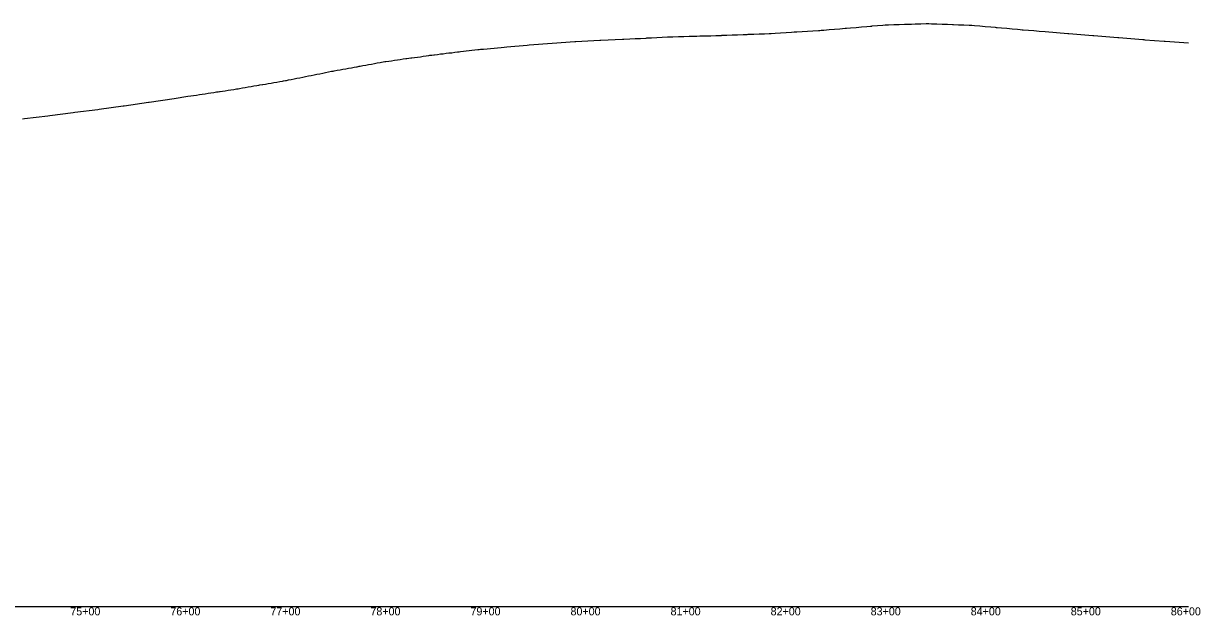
# Model space of a CAD drawing. Extents: x 49922 to 54713, y 49991 to 62800.
# Drawn here: x 53436 to 54612, y 49991 to 50583 of the extents above; entities that cross this region are included whole.
import ezdxf

# ---------------------------------------------------------------- set-up
doc = ezdxf.new("R2010")
doc.units = 0
for name, color, linetype in [('RD_DDB_Profile_EX', 7, 'Continuous'), ('RD_DDB_StaTX', 7, 'Continuous'), ('RD_GPK_Profile_Cell', 7, 'Continuous')]:
    doc.layers.add(name, color=color, linetype=linetype)

msp = doc.modelspace()

# ---------------------------------------------------------------- linework, layer by layer
at = {"layer": 'RD_DDB_Profile_EX'}
for points in [[(54052.5, 50567.8), (54057.9, 50568.1), (54058.6, 50568.2), (54060.7, 50568.2), (54063.3, 50568.4), (54068.6, 50568.6), (54074, 50568.9), (54079.4, 50569.2), (54081.6, 50569.3), (54083.8, 50569.4), (54084.8, 50569.4), (54090.2, 50569.6), (54095.6, 50569.7), (54100.9, 50569.9), (54106, 50570), (54106.3, 50570), (54108.8, 50570.1), (54111.7, 50570.2), (54117.1, 50570.3), (54122.5, 50570.5), (54127.8, 50570.7), (54130.7, 50570.7), (54133.2, 50570.8), (54133.6, 50570.9), (54138.6, 50571), (54144, 50571.2), (54149.4, 50571.5), (54154.8, 50571.7), (54155.7, 50571.7), (54158.6, 50571.8), (54159.1, 50571.8), (54160.1, 50571.9), (54165.5, 50572.1), (54170.9, 50572.3), (54176.3, 50572.5), (54181, 50572.7), (54181.7, 50572.7), (54183, 50572.8), (54187.1, 50573.1), (54192.4, 50573.4), (54197.8, 50573.7), (54203.2, 50574.1), (54205.8, 50574.2), (54208, 50574.4), (54208.6, 50574.4), (54214, 50574.7), (54219.4, 50575.1), (54224.7, 50575.4), (54230.1, 50575.8), (54231.6, 50575.8), (54233, 50575.9), (54233.4, 50576), (54235.5, 50576.1), (54240.9, 50576.6), (54246.3, 50577), (54251.6, 50577.5), (54257, 50577.9), (54258.4, 50578), (54262.4, 50578.4), (54267.8, 50578.8), (54273.2, 50579.3), (54278.6, 50579.7), (54282.1, 50580), (54283.4, 50580.1), (54283.9, 50580.2), (54289.3, 50580.6), (54294.7, 50581.1), (54296.8, 50581.2), (54297.3, 50581.3), (54300.1, 50581.4), (54305.5, 50581.6), (54310.9, 50581.7), (54316.2, 50581.9), (54320.9, 50582.1), (54321.6, 50582.1), (54322.3, 50582.1), (54323.2, 50582.1), (54327, 50582.2), (54332.4, 50582.4), (54337.8, 50582.6), (54339.2, 50582.6), (54340.6, 50582.6), (54343.1, 50582.5), (54348.5, 50582.3), (54353.9, 50582.1), (54359.3, 50581.9), (54364.2, 50581.7), (54364.7, 50581.7), (54365.3, 50581.7), (54370.1, 50581.5), (54375.4, 50581.3), (54380.8, 50581.1), (54381.9, 50581), (54383.4, 50580.9), (54386.2, 50580.7), (54391.6, 50580.2), (54397, 50579.7), (54402.4, 50579.3), (54406.9, 50578.9), (54407.7, 50578.8), (54408.9, 50578.7)], [(54408.9, 50578.7), (54413.1, 50578.3), (54418.5, 50577.9), (54423.9, 50577.4), (54429.3, 50576.9), (54431.9, 50576.7), (54433.9, 50576.5), (54434.7, 50576.5), (54440, 50576), (54445.4, 50575.6), (54450.8, 50575.1), (54456.9, 50574.6), (54479.4, 50572.8), (54480.5, 50572.6), (54504.4, 50570.7), (54505.5, 50570.6), (54529.4, 50568.7), (54530.5, 50568.6), (54554.5, 50566.7), (54555.5, 50566.6), (54556.3, 50566.5), (54575.7, 50565), (54576.7, 50564.9), (54600, 50563.5)], [(53691.8, 50524.6), (53694.6, 50525), (53695.5, 50525.2), (53697.5, 50525.6), (53698.5, 50525.8), (53700.4, 50526.2), (53703.2, 50526.8), (53706.1, 50527.3), (53709, 50527.9), (53711.8, 50528.5), (53714.7, 50529.1), (53717.6, 50529.7), (53720.4, 50530.2), (53723.3, 50530.8), (53726.2, 50531.4), (53729, 50532), (53731.9, 50532.5), (53734.8, 50533.1), (53737.6, 50533.7), (53740.5, 50534.2), (53743.6, 50534.9), (53745.1, 50535.1), (53746.2, 50535.3), (53749.1, 50535.9), (53752, 50536.4), (53754.8, 50536.9), (53757.7, 50537.4), (53760.6, 50538), (53763.4, 50538.5), (53766.3, 50539), (53768.6, 50539.4), (53769.2, 50539.5), (53771.2, 50539.9), (53772, 50540), (53774.9, 50540.6), (53777.8, 50541.1), (53780.6, 50541.6), (53783.5, 50542.1), (53786.4, 50542.7), (53789.2, 50543.2), (53792.1, 50543.7), (53793.6, 50544), (53795.2, 50544.3), (53796.8, 50544.6), (53797.8, 50544.7), (53800.7, 50545.1), (53803.6, 50545.5), (53806.5, 50545.9), (53809.3, 50546.3), (53812.2, 50546.7), (53815.1, 50547.2), (53817.9, 50547.6), (53818.8, 50547.7), (53820.8, 50547.9), (53822.9, 50548.2), (53823.7, 50548.3), (53826.5, 50548.7), (53829.4, 50549.1), (53832.3, 50549.5), (53835.1, 50549.9), (53838, 50550.3), (53840.9, 50550.7), (53841.8, 50550.9), (53843.1, 50551), (53843.7, 50551.1), (53845.7, 50551.4), (53846.6, 50551.5), (53849.5, 50551.8), (53852.3, 50552.2), (53855.2, 50552.5), (53858.1, 50552.9), (53860.9, 50553.2), (53863.8, 50553.5), (53866.7, 50553.9), (53869.5, 50554.2), (53871, 50554.4), (53872.4, 50554.6), (53875.3, 50554.9), (53878.1, 50555.2), (53881, 50555.6), (53883.9, 50555.9), (53886.7, 50556.2), (53889.9, 50556.6), (53891.1, 50556.7), (53892.5, 50556.9), (53895.3, 50557.1), (53913.1, 50558.8), (53916.1, 50559), (53918.6, 50559.2), (53939.1, 50561.1), (53941.1, 50561.2), (53964.1, 50563), (53986.6, 50564.8), (53987.8, 50564.8), (54011.6, 50565.9), (54012.8, 50566), (54034.4, 50566.9), (54035.7, 50567), (54041.7, 50567.3), (54047.1, 50567.6), (54052.5, 50567.8)], [(53434.6, 50487.4), (53436.8, 50487.7), (53459.9, 50490.5), (53461.8, 50490.8), (53485.2, 50493.7), (53486.8, 50493.9), (53510, 50496.7), (53511.2, 50496.9), (53535.3, 50500.4), (53536.2, 50500.5), (53560.6, 50504.1), (53561.2, 50504.2), (53586.3, 50507.8), (53600, 50509.9), (53602.9, 50510.3), (53605.7, 50510.7), (53608.6, 50511.1), (53611.5, 50511.6), (53614.3, 50512), (53617.2, 50512.4), (53620.1, 50512.9), (53622.9, 50513.3), (53625.8, 50513.7), (53628.7, 50514.2), (53630.2, 50514.4), (53631.5, 50514.6), (53632.3, 50514.8), (53634.4, 50515.1), (53637.3, 50515.5), (53640.1, 50516), (53643, 50516.4), (53645.9, 50516.8), (53648.7, 50517.3), (53650.1, 50517.5), (53651.6, 50517.8), (53654.5, 50518.3), (53657.3, 50518.8), (53660.2, 50519.3), (53663.1, 50519.7), (53665.9, 50520.2), (53668.8, 50520.7), (53670.7, 50521), (53671.7, 50521.2), (53674.6, 50521.7), (53674.9, 50521.7), (53677.4, 50522.1), (53680.3, 50522.6), (53683.2, 50523.1), (53686, 50523.6), (53688.9, 50524.1), (53691.8, 50524.6)]]:
    msp.add_lwpolyline(points, dxfattribs=at)
at = {"layer": 'RD_GPK_Profile_Cell'}
msp.add_line((50000, 50000), (54600, 50000), dxfattribs=at)

# ---------------------------------------------------------------- texts
at = {"layer": 'RD_DDB_StaTX'}
for s, p in [('75+00', (53482.4, 49991)), ('76+00', (53582.4, 49991)), ('77+00', (53682.4, 49991)), ('78+00', (53782.4, 49991)), ('79+00', (53882.4, 49991)), ('80+00', (53982.4, 49991)), ('81+00', (54082.4, 49991)), ('82+00', (54182.4, 49991)), ('83+00', (54282.4, 49991)), ('84+00', (54382.4, 49991)), ('85+00', (54482.4, 49991)), ('86+00', (54582.4, 49991))]:
    msp.add_text(s, height=8, dxfattribs=at).set_placement(p)

doc.saveas('drawing.dxf')
